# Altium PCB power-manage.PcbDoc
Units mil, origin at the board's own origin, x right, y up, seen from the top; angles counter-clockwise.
Board outline 3395.41 x 2057.23 mil, 4 copper layers (Top Layer, POWER, GND, Bottom Layer), stack 22.4 mil thick; 64 components, 38 nets, 210 pads, 100 vias.
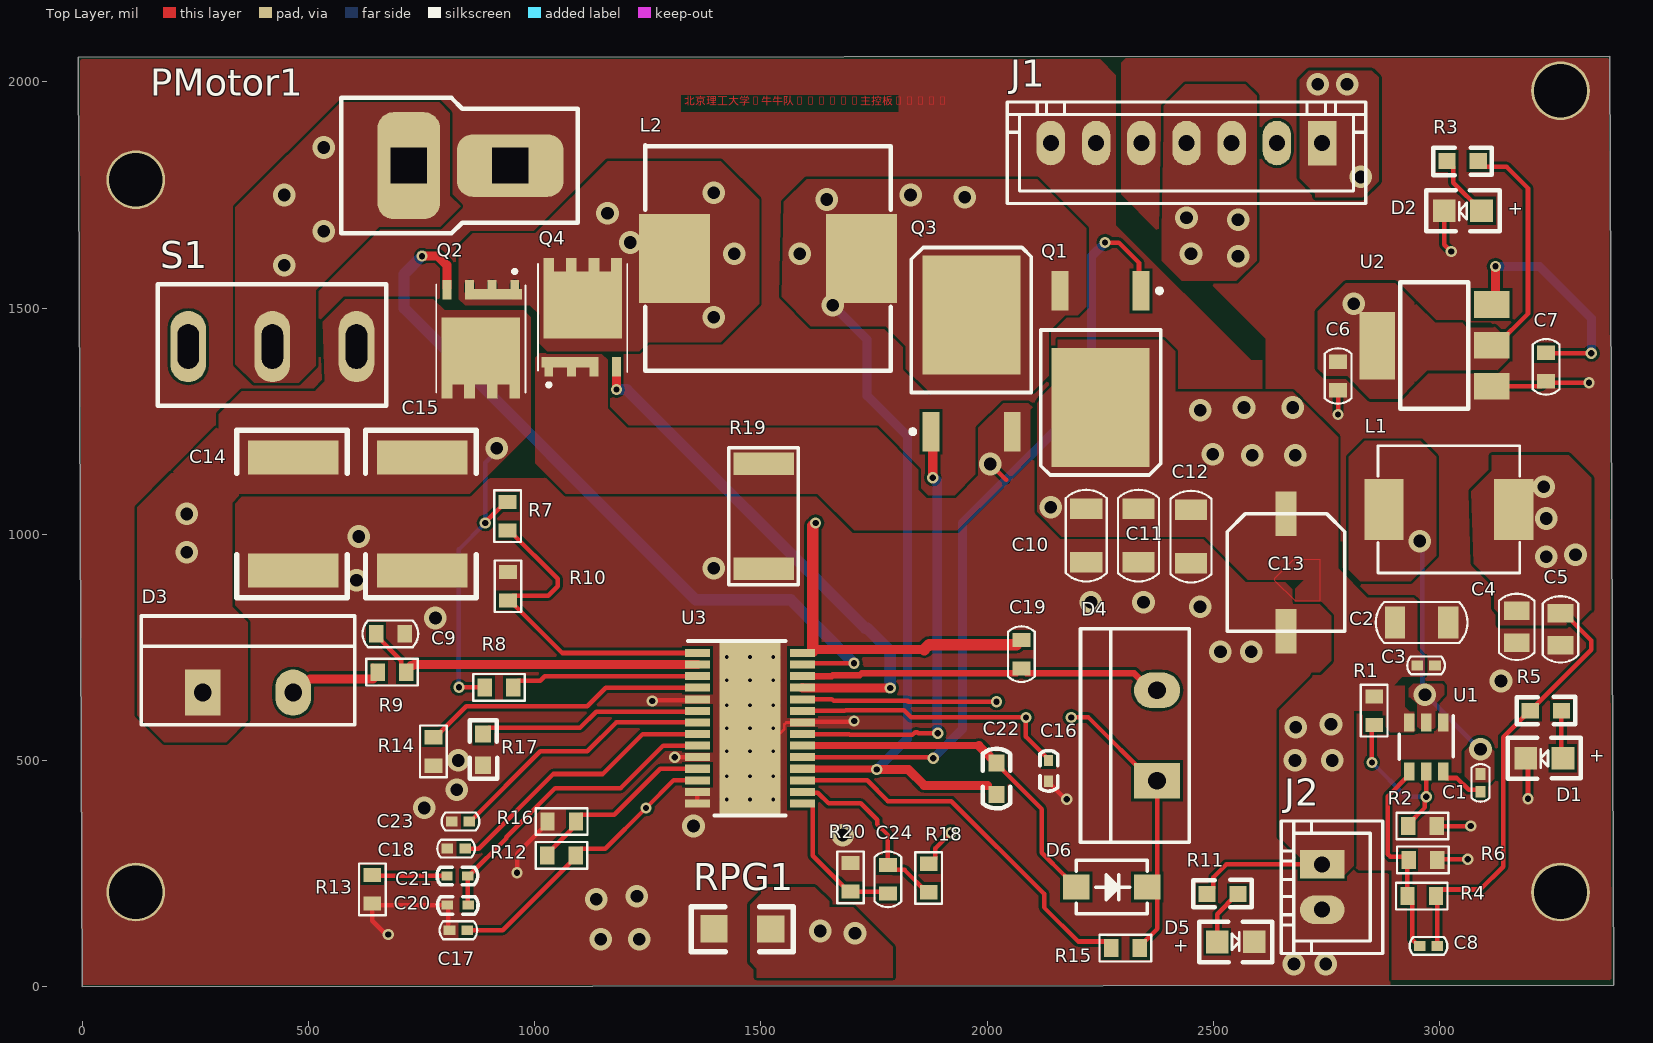
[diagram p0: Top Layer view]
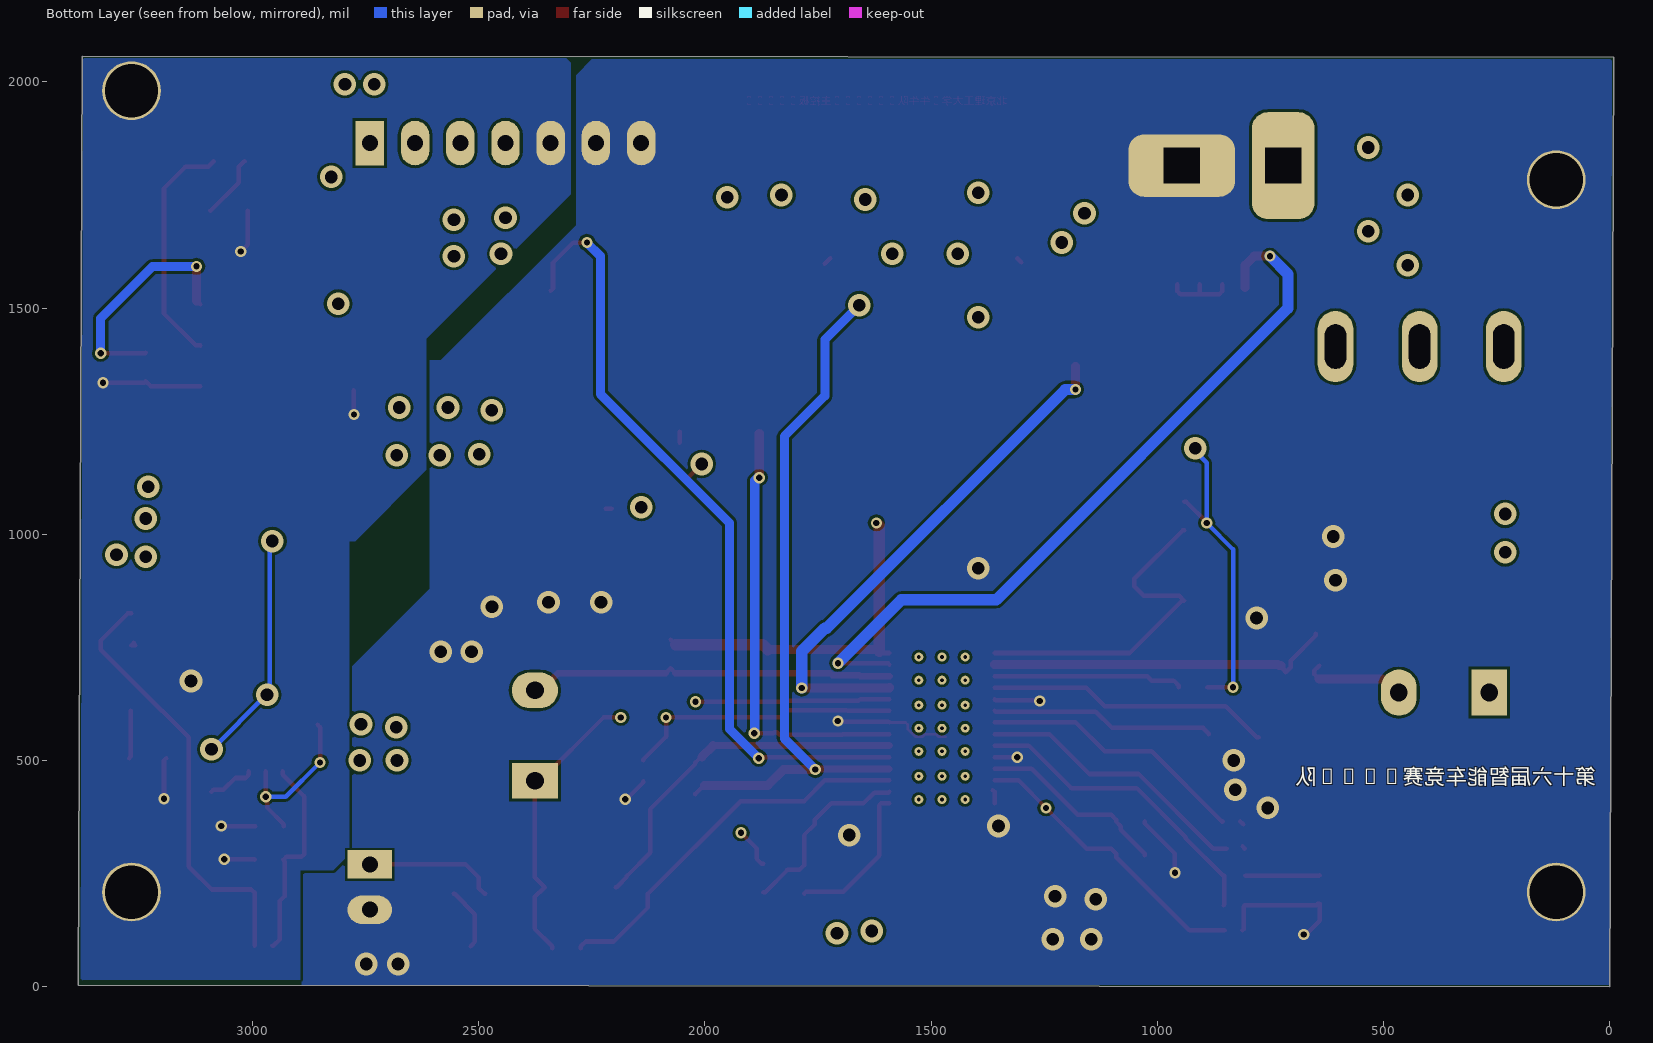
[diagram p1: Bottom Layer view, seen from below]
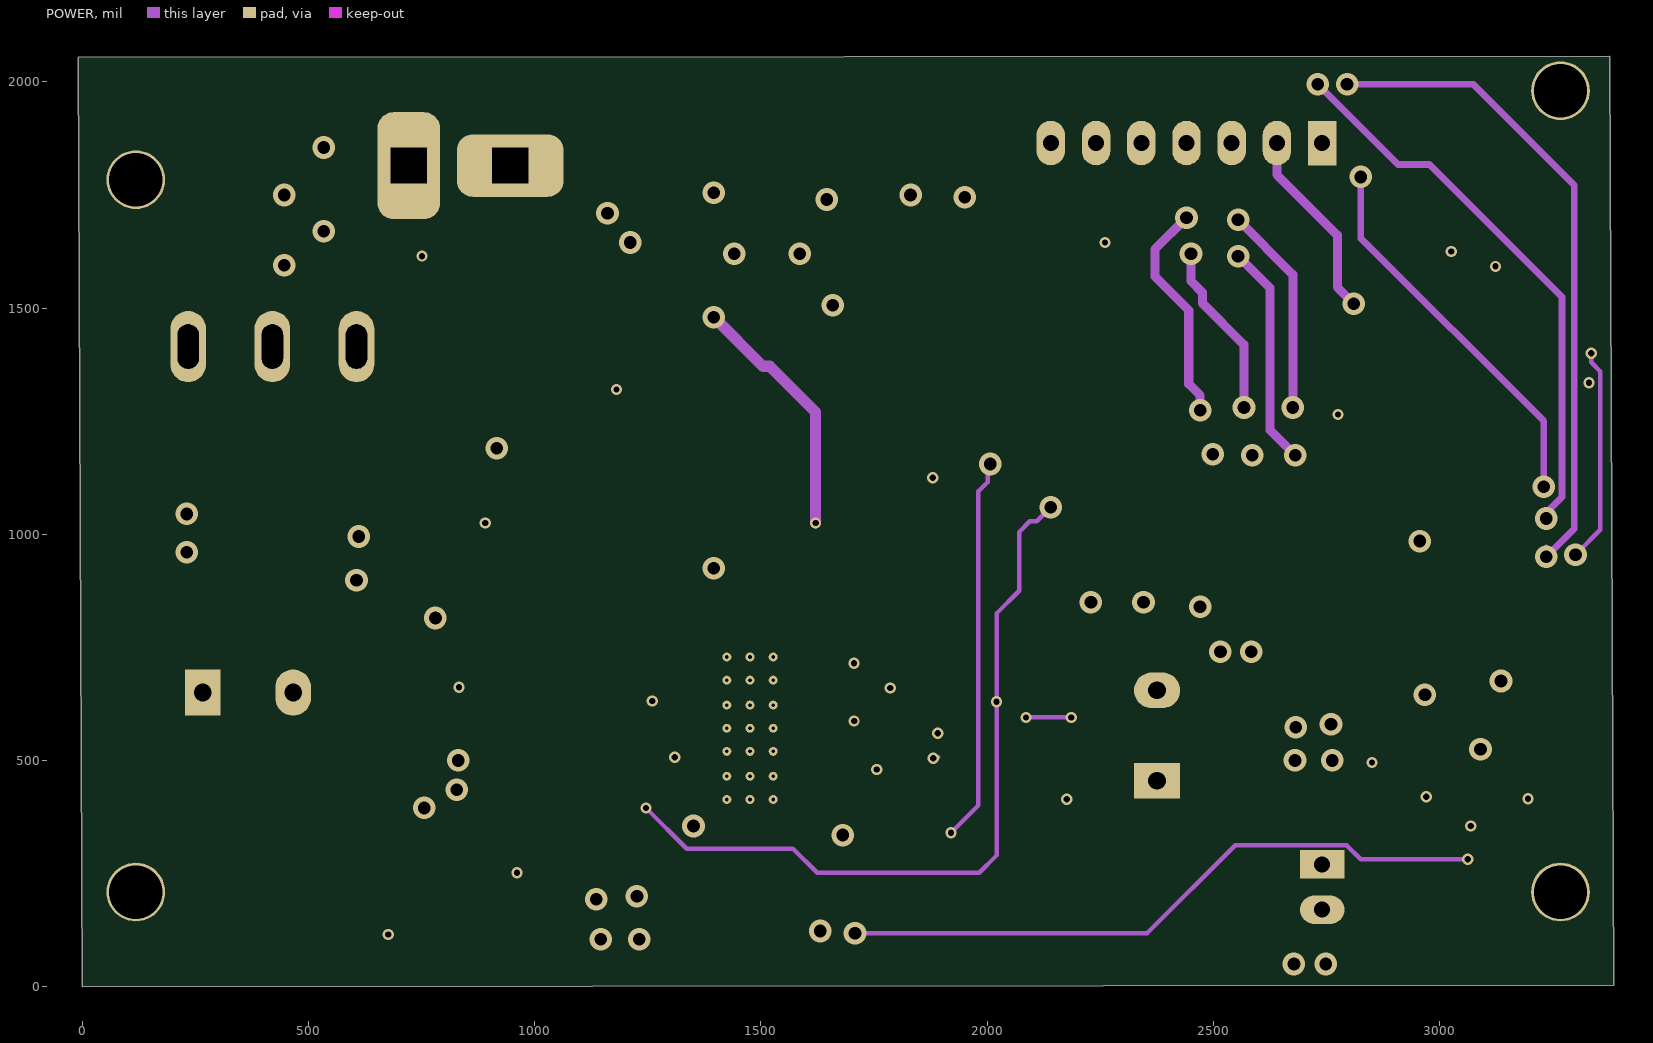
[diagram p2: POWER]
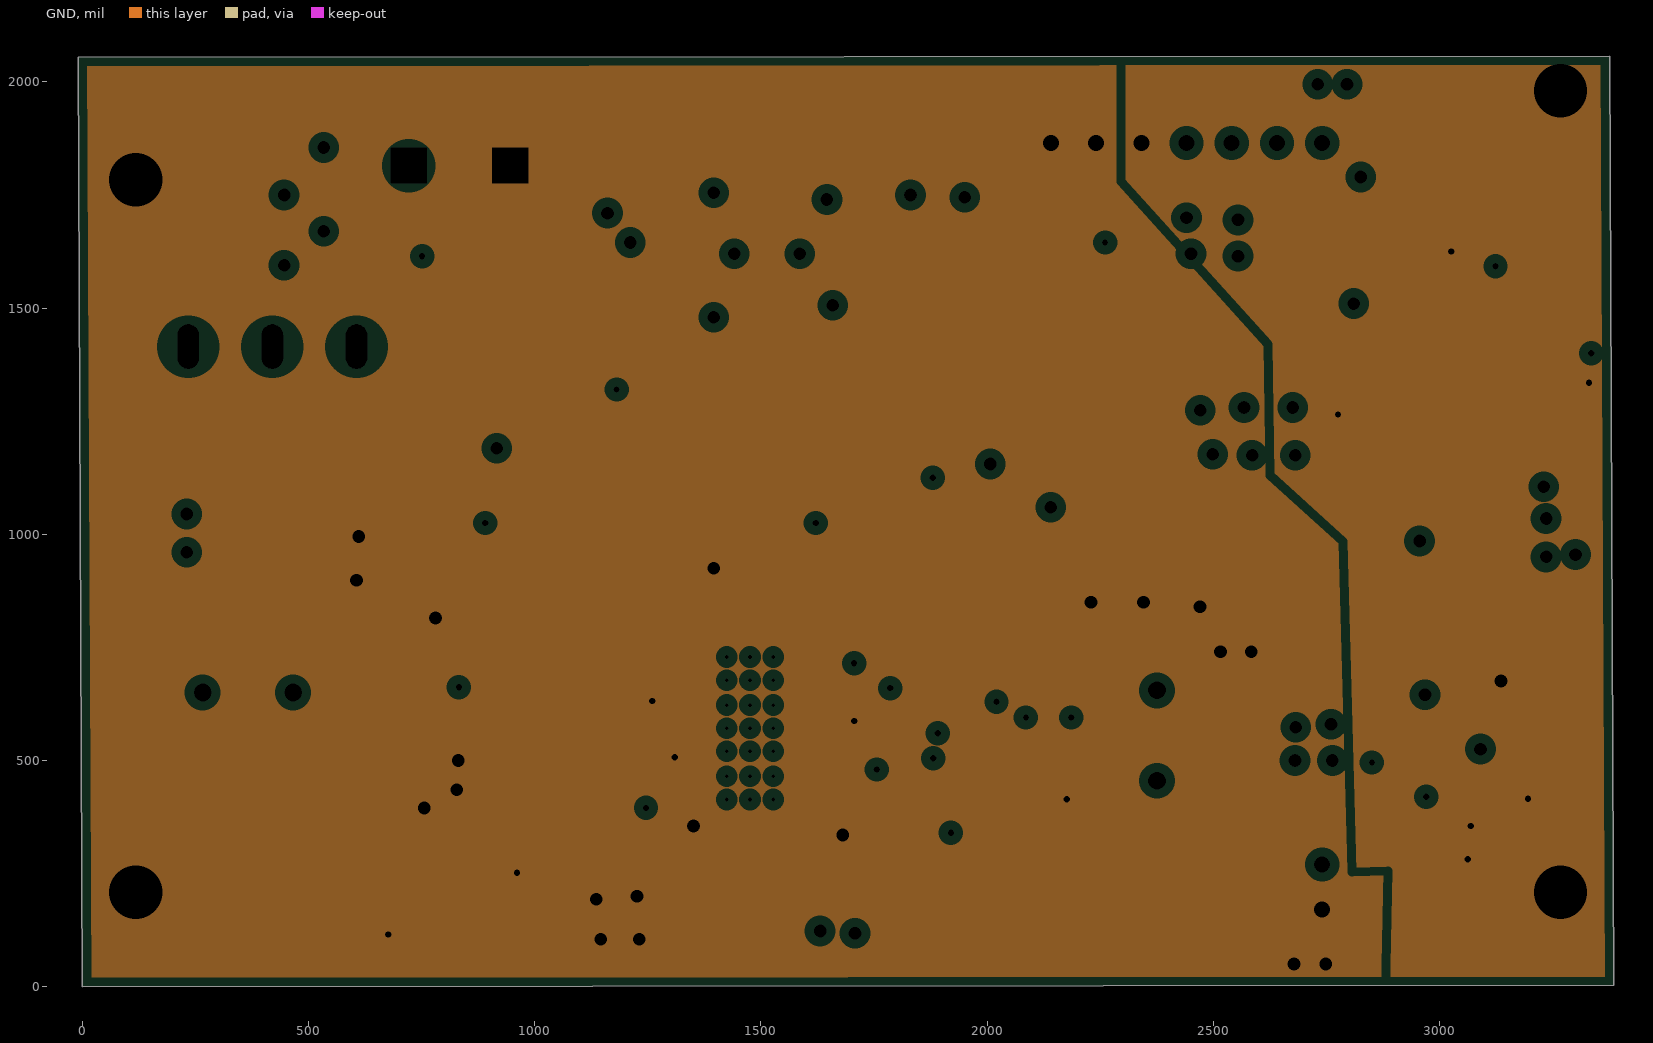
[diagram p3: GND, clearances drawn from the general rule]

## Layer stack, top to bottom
Top Solder: solder mask 0.4, Solder Resist, Dk 3.5
Top Layer: signal copper 1.4
Dielectric 2: prepreg 2.8, PP-006, Dk 4.1
POWER: signal copper 0.7
Dielectric 3: prepreg 2.8, PP-006, Dk 4.1
GND: plane copper 0.7, net AGND
Dielectric 1: dielectric 12.6, FR-4, Dk 4.8
Bottom Layer: signal copper 1.4
Bottom Solder: solder mask 0.4, Solder Resist, Dk 3.5

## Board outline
0,0 -9.59,2054.52 3376.24,2057.23 3385.83,2.71

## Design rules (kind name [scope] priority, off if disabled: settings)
Clearance [All] p1: gap=6 ignorepadtopadclearanceinfootprint=TRUE
HoleSize [All] p1: absolutevalues=TRUE maxlimit=400 minlimit=1 maxpercent=80.000 minpercent=20.000
MinimumSolderMaskSliver [All] p1: minsoldermaskwidth=2
PlaneClearance [All] p1: clearance=20
PlaneConnect [All] p1: planeconnectstyle=Direct reliefexpansion=20 reliefentries=4 reliefconductorwidth=10 reliefairgap=10
PolygonConnect [All] p1: connectstyle=Direct reliefconductorwidth=10 reliefentries=4 polygonreliefangle="90 Angle" airgapwidth=10
RoutingVias [All] p1: holewidth=14 width=25 viastyle="Through Hole" minholewidth=3 minwidth=3 maxholewidth=118.11 maxwidth=200
SilkToSilkClearance [All] p1: silktosilkclearance=2
SilkToSolderMaskClearance [IsPad] p1: minsilkscreentomaskgap=2 clearancetoexposedcopper=TRUE
SolderMaskExpansion [All] p1: expansion=4
Width [All] p1: maxlimit=100 minlimit=6 preferedwidth=10 toplayer_maxwidth=50 bottomlayer_maxwidth=50 minimp=50.000000 maximp=50.000000 favimp=50.000000
24 further rules are at their usual default settings.

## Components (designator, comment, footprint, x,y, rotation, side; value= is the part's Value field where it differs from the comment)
C1 "Cap" 0402-C 3090.89,450.36 r270 top value=0.1uF
C2 "Cap" 1206-C 2960.89,805.05 r180 top value=10uF
C3 "Cap" 0402-C 2970.58,710.05 r180 top value=0.1uF
C4 "Cap" 0805-C 3170.89,795.48 r270 top value=22uF
C5 "Cap" 0805-C 3267.76,790.05 r270 top value=22uF
C6 "Cap" 0603-C 2775.89,1350.05 r90 top value=10uF
C7 "Cap" 0603-C 3235.89,1370.05 r90 top value=10uF
C8 "Cap" 0402-C 2975.89,90.05 r180 top value=100pF
C9 "Cap" 0603-C 680.89,780.05 r180 top value=0.1uF
C10 "Cap" 1206-C 2219.24,997.01 r270 top value=22uF
C11 "Cap" 1206-C 2334.79,997.01 r270 top value=22uF
C12 "Cap" 1206-C 2450.89,995.05 r270 top value=22uF
C13 "Cap" "CAP-E SMD 6.6X6.6" 2660.89,785.21 r180 top value=270uF
C14 "C" C2220 465.89,1170.05 r270 top value=15uF
C15 "C" C2220 750.89,1170.05 r270 top value=15uF
C16 "Cap" C0402 2135.89,499.05 r270 top value="1uF 1mO"
C17 "Cap" 0402-C 831.21,124.57 r180 top value=0.1uF
C18 "Cap" 0402-C 826.21,305.05 r180 top value=15nF
C19 "Cap" 0603-C 2075.89,735.05 r270 top value=0.1uF
C20 "Cap" C0402 851.89,180.05 r180 top value=330pF
C21 "Cap" C0402 850.89,245.05 r180 top value=33nF
C22 "Cap" C0603 2020.89,425.05 r90 top value=100nF
C23 "Cap" 0402-C 835.89,365.05 r0 top value=470pF
C24 "Cap" 0603-C 1780.89,237.19 r270 top value=47pF
D1 "LED0" LED0805 3273.19,505.25 r180 top
D2 "LED0" LED0805 3093.19,1715.25 r180 top
D3 "SDURF" TO-220-AS 365.89,650.05 r0 top
D4 "STTH" TO-220-AS 2375.89,555.05 r90 top
D5 "LED0" LED0805 2508.59,98.73 r0 top
D6 "MBR0520" SOD-123 2275.66,220.05 r0 top
J1 "PIN7" XH7-2.54 2440.89,1865.05 r180 top
J2 "PIN2" XH2-2.54 2740.89,220.05 r270 top
L1 "Inductor Iron" IND-SMD_L7.8-W7.0_MAPM0630F 3020.89,1055.05 r180 top value=15uH
L2 "Inductor" IND-SMD_L13.8-W12.6_MHCC12050 1515.89,1610.05 r0 top value=4.7uH
PMotor1 "Header 2" PCBComponent_1 571.88,1964.66 r270 top
Q1 "BSC034N10LS5" TO252 2250.89,1365.05 r270 top
Q2 "BSC034N10LS5" BSC010N04LS6ATMA1 880.89,1431.62 r180 top
Q3 "BSC034N10LS5" TO252 1965.89,1400.05 r90 top
Q4 "BSC034N10LS5" BSC010N04LS6ATMA1 1105.89,1480.05 r0 top
R1 "Res1" 0603-R 2855.89,610.05 r90 top value=510K
R2 "Res1" 0603-R 2962.39,355.05 r180 top value=100K
R3 "Res2" R0603 3016.89,1825.05 r0 top value=40
R4 "Res1" 0603-R 2960.89,200.05 r0 top value=100K
R5 "Res2" R0603 3269.89,610.05 r180 top value=400
R6 "Res1" 0603-R 2963.49,280.05 r180 top value=13K
R7 "Res1" 0603-R 939.83,1040.05 r90 top value=270K
R8 "Res1" 0603-R 920.89,661.55 r180 top value=2K
R9 "10R" 0603-R 684.4,695.05 r180 top
R10 "Res1" 0603-R 940.89,885.05 r270 top value=180K
R11 "Res2" R0603 2554.89,205.05 r180 top value=1.6K
R12 "Res1" 0603-R 1059.24,290.05 r0 top value=270K
R13 "Res1" 0603-R 640.89,215.05 r90 top value=10K
R14 "Res1" 0603-R 775.89,520.05 r90 top value=91K
R15 "Res1" 0603-R 2305.89,85.05 r0 top value=270K
R16 "Res1" 0603-R 1059.59,365.05 r180 top value=20K
R17 "Res1" R0603 885.89,489.44 r90 top value=27K
R18 "Res1" 0603-R 1870.89,240.05 r270 top value=100R
R19 "Res1" 2512-R 1505.89,1040.05 r90 top value=3.44mR
R20 "Res1" 0603-R 1698.1,241.55 r270 top value=100R
RPG1 "Res2" R1206 1450.89,130.05 r180 top value=0Ω
S1 "SW-SPDT" SW-TO3 419.89,1415.05 r270 top
U1 "TPS54202DDCR" DDC0006A_N 2970.89,530.05 r270 top value=Value
U2 "AMS1117-3.3V" SOT223 2985.89,1415.05 r90 top
U3 "LM5176PWPR" PWP0028C_N 1475.89,571.23 r0 top value=Value

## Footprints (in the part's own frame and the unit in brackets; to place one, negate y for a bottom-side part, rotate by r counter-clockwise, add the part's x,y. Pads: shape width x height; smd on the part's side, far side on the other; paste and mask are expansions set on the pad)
0402-C [mm]
  rect 0.65x0.55 smd: 1(-0.5,0) 2(0.5,0)
  silkscreen extent -1.06,-0.5 1.06,0.5
0603-C [mm]
  rect 0.8x1 smd: 1(-0.8,0) 2(0.8,0)
  silkscreen extent -1.56,-0.75 1.56,0.75
0603-R [mm]
  rect 0.8x1 smd: 1(-0.8,0) 2(0.8,0)
  silkscreen extent -1.45,-0.75 1.45,0.75
0805-C [mm]
  rect 1.05x1.45 smd: 1(-0.9,0) 2(0.9,0)
  silkscreen extent -1.86,-1 1.86,1
1206-C [mm]
  rect 1.15x1.8 smd: 1(-1.5,0) 2(1.5,0)
  silkscreen extent -2.58,-1.15 2.58,1.15
2512-R [mm]
  rect 1.25x3.4 smd: 1(-2.95,0) 2(2.95,0)
  silkscreen extent -3.85,-1.95 3.85,1.95
BSC010N04LS6ATMA1 [mm]
  rect 0.5x1.1 smd: 1(1.905,-2.775)
  rect 0.6x0.8 smd: 2(-1.905,2.925) 2(-0.635,2.925) 2(0.635,2.925) 2(1.905,2.925)
  rect 4.41x3.75 smd: 2(0,0.675)
  rect 0.5x0.5 smd: 3(-1.905,-3.075) 3(-0.635,-3.075) 3(0.635,-3.075)
  rect 3.2x0.6 smd: 3(-0.715,-2.525)
  silkscreen extent -2.5,-3.9 2.5,3, body extent -2.5,-3.27 2.5,3.26, height 1.2
C0402 [mil]
  rect 25x20 smd: 1(-1,0) 2(45,0)
  silkscreen extent -23,-19 67,20, body extent 2,-10 42,10, height 20
C0603 [mil]
  rect 38x35 smd: 1(0,0) 2(69,0)
  silkscreen extent -31,-30 101,30, body extent 4,-16 67,16, height 12
C2220 [mil]
  rect 75x200 smd: 1(0,0) 2(250,0)
  silkscreen extent -60,-125 310,120, body extent 11,-98 235,98, height 91
"CAP-E SMD 6.6X6.6" [mm] "SMDC"
  rect 1.2x2.5 smd: 1(0,0) 2(0,-6.6)
  silkscreen extent -3.3,-6.6 3.3,0, body extent -3.27,-6.8 3.33,0.2, height 5.2
DDC0006A_N [mm]
  rect 1x0.6 smd paste+0 mask+0: 1(-1.375,0.95) 2(-1.375,0) 3(-1.375,-0.95) 4(1.375,-0.95) 5(1.375,0) 6(1.375,0.95)
  silkscreen extent -1.75,-1.52 0.7,1.53, body extent 0,0 0.25,0.25, height 0.25
IND-SMD_L7.8-W7.0_MAPM0630F [mm]
  rect 2.194x3.42 smd: 1(3.643,0) 2(-3.643,0)
  silkscreen extent -3.98,-3.58 3.98,3.58
IND-SMD_L13.8-W12.6_MHCC12050 [mm]
  rect 4x5 smd: 1(-5.25,0) 2(5.25,0)
  silkscreen extent -6.9,-6.3 6.9,6.35
LED0805 [mil] "1/8W"
  rect 50x50 smd: 1(0,0) 2(82.3,0.2)
  silkscreen extent -40,-45 122,45, body extent 2,-25 80,25, height 20
PCBComponent_1 [mm]
  rrect50% 6x3.5 hole 2 square: 1(3.8,3.8)
  rrect50% 3.5x6 hole 2 square: 2(3.8,9.5)
  silkscreen extent 0,0 7.6,13.3
PWP0028C_N [mm]
  rect 1.4x0.45 smd paste+0 mask+0: 1(-2.95,4.225) 2(-2.95,3.575) 3(-2.95,2.925) 4(-2.95,2.275) 5(-2.95,1.625) 6(-2.95,0.975) 7(-2.95,0.325) 8(-2.95,-0.325) 9(-2.95,-0.975) 10(-2.95,-1.625) 11(-2.95,-2.275) 12(-2.95,-2.925) 13(-2.95,-3.575) 14(-2.95,-4.225) 15(2.95,-4.225) 16(2.95,-3.575) 17(2.95,-2.925) 18(2.95,-2.275) 19(2.95,-1.625) 20(2.95,-0.975) 21(2.95,-0.325) 22(2.95,0.325) 23(2.95,0.975) 24(2.95,1.625) 25(2.95,2.275) 26(2.95,2.925) 27(2.95,3.575) 28(2.95,4.225)
  rect 3.4x9.7 smd paste-1.7 mask-1.702: 29(0,0)
  round 0.5 hole 0.203 mask-0.152: V(-1.3,-1.3) V(-1.3,0) V(-1.3,1.3) V(0,-1.3) V(0,0) V(0,1.3) V(1.3,-1.3) V(1.3,0) V(1.3,1.3)
  round 0.5 hole 0.203 mask-0.241: V(-1.3,2.7) V(-1.3,4) V(-1.3,-4) V(-1.3,-2.7) V(0,2.7) V(0,-2.7) V(0,4) V(0,-4) V(1.3,2.7) V(1.3,4) V(1.3,-4) V(1.3,-2.7)
  silkscreen extent -3.5,-4.9 2,4.9, body extent 0,0 0.25,0.25, height 0.25
R0603 [mil] "1/10W"
  rect 38x35 smd: 1(0,0) 2(69,0)
  silkscreen extent -30,-31 99,30, body extent 4,-16 66,16, height 18
R1206 [mil] "1/4W"
  rect 60x60 smd: 1(-71,3) 2(55,2)
  silkscreen extent -121,-47 105,53, body extent -71,-29 55,33, height 24
SOD-123 [mm]
  rect 1.5x1.4 smd: 1(2,0) 2(-2,0)
  silkscreen extent -2,-1.5 2,1.5
SOT223 [mil]
  rect 59x79 smd: 1(-88,-130) 2(2.55,-130) 3(93.1,-130)
  rect 150x79 smd: 2(1.88,123.54)
  silkscreen extent -137,-78 143,72, body extent -126,-139 130,135, height 67
SW-TO3 [mm]
  oval 4x2 hole 1.2 slot 2.5 at 0 deg: 1(0,-4.724) 2(0,0) 3(0,4.724)
  silkscreen extent -3.5,-6.43 3.33,6.39, body extent -3.43,-6.36 3.43,6.35, height 28.55
TO252 [mm] "D-PAK  / SOT-428"
  rect 2.2x0.95 smd: 1(-4.4,2.28) 3(-4.4,-2.28)
  rect 6.7x5.5 smd: 2(2.15,0)
  silkscreen extent -4.52,-3.35 5.94,3.43, body extent -4.47,-3.3 4.78,3.3, height 2.31
TO-220-AS [mm]
  rect 2x2.6 hole 1: 1(-2.54,0)
  oval 2x2.6 hole 1: 2(2.54,0)
  silkscreen extent -6,-1.8 6,4.3
XH2-2.54 [mm]
  rect 1.6x2.5 hole 0.9: 1(-1.27,0)
  oval 1.6x2.5 hole 0.9: 2(1.27,0)
  silkscreen extent -3.72,-2.3 3.72,3.4
XH7-2.54 [mm]
  rect 1.6x2.5 hole 0.9: 1(-7.62,0)
  oval 1.6x2.5 hole 0.9: 2(-5.08,0) 3(-2.54,0) 4(0,0) 5(2.54,0) 6(5.08,0) 7(7.62,0)
  silkscreen extent -10.07,-2.3 10.07,3.4

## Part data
C1 C2 C3 C4 C5 C6 C7 C8 C9 C10 C11 C12 C13 C16 C17 C18 C19 C20 C21 C22 C23 C24: "Capacitor"
C14 C15: library part "Cap Pol1", "Polarized Capacitor (Radial)"
D1 D2 D5: "Typical INFRARED GaAs LED"
D3 D4 D6: library part "Diode 1N4003", "1 Amp General Purpose Rectifier"
L1: "Magnetic-Core Inductor"
PMotor1: "Header, 2-Pin"
Q1 Q2 Q3 Q4: library part NMOS-2, "N-Channel Power MOSFET"
R1 R2 R3 R4 R5 R6 R7 R8 R10 R11 R12 R13 R14 R15 R16 R17 R18 R19 R20 RPG1: "Resistor"
R9: library part Res1, "Resistor"
S1: "SPDT Subminiature Toggle Switch, Right Angle Mounting, Vertical Actuation"
U1 U3: "No Description Available", Manufacturer="Texas Instruments"
U2: library part AMS1117

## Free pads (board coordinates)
  round 129.92 hole 118.11: 4(118.13,209.08) 4(118.13,1783.88) 4(3267.74,209.08) 4(3267.74,1980.73)

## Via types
v1: diameter 50, hole 28, Top Layer to Bottom Layer, 67 vias
v2: diameter 25, hole 14, Top Layer to Bottom Layer, 33 vias

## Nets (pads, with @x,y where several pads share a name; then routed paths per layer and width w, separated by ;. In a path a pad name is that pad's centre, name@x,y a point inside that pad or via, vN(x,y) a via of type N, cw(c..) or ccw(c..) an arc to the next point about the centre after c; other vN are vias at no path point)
AGND: C9.1 C10.2 C11.2 C12.2 C13.1 C14.2 C15.2 C16.2 C17.2 C18.2 C20.2 C23.1 D5.2 J1.6 J1.7 J2.2 pad.4@118.13,209.08 pad.4@118.13,1783.88 PMotor1.2 R10.1 R13.1 R14.1 R16.2 R17.1 R19.1 R20.1 RPG1.2 U3.5 U3.10 U3.13 U3.14 U3.22 U3.29 | length 970.5
  Top Layer w6: U3.29@1468.09,552.39 1483.7,552.39 1489.22,557.91 1513.75,557.91 1519.27,552.39 1534.88,552.39 1551.82,569.33 1551.82,579.61 1556.24,584.03 U3.22
  Top Layer w10: v2(675.89,115.05) 671.83,115.05 640.89,145.99 R13.1 644.83,183.55 648.33,180.05 C20.2 809.21,177.73 809.21,126.89 C17.2 ; C18.2 C18.2@811.37,309.89 ; C23.1@810.38,359.22 811.37,360.21 C23.1 ; v2(960.89,251.55) 960.89,293.91 1028.1,361.11 R16.2 ; v2(1259.57,631.53) 1261.41,633.37 1357.91,633.37 U3.5 ; v2(1309.62,507.25) U3.10 ; U3.14 U3.13 U3.13@1363.61,434.34 ; U3.22 1593.64,585.63 1704.4,585.63 v2(1706,587.23) ; C16.2 2135.89,451.55 2173.39,414.05 v2(2175.89,414.05)
  other v1: 2678.39,50.05 2748.39,50.05 1145.89,105.05 1230.89,105.05 1135.89,193.05 1225.89,200.05 1681.24,335.05 1350.89,355.05 755.89,395.05 827.37,435.36 830.89,500.05 2515.89,740.05 2583.74,740 780.46,815.05 2470.89,840.05 2229.61,850.05 2345.89,850.05 605.89,898.47 1395.89,925.05 610.89,995.05
NetC1_1: C1.1 L1.1 U1.2 | length 532.1
  Bottom Layer w10: v1(2956.21,985.05) 2962.12,979.14 2962.12,650.96 v1(2968.02,645.05) ; v1@2968.02,659.66 v1(2968.02,645.05) ; v1(3090.89,525.05) 3089.46,525.05 2969.46,645.05 v1(2968.02,645.05)
NetC1_2: C1.2 U1.6 | length 105.9
  Top Layer w10: U1.6 3008.29,468.04 3015.11,461.23 3038.71,461.23 3065.07,434.87 3086.7,434.87 C1.2
NetC8_2: C8.2 R4.1 R6.2 U1.4 | length 457.6
  Top Layer w10: U1.4 2933.49,468.04 2885.89,420.44 2885.89,292.77 2891.75,286.91 2925.14,286.91 R6.2 2929.4,277.45 R4.1 2940.14,189.3 2940.14,104.14 2954.24,90.05 C8.2
NetC9_2: C9.2 R9.1 U3.2 | length 765.7
  Top Layer w10: C9.2 649.4,776.11 705.14,720.36 705.14,705.8 R9.1 720.89,700.05 720.89,703.99 R9.1@726.64,709.73 ; R9.1@730.58,709.73 732.82,711.98
  Top Layer w20: R9.1@726.64,709.73 R9.1@730.58,709.73 ; 732.82,711.98 U3.2
NetC18_1: C18.1 U3.8 | length 618.8
  Top Layer w10: C18.1 875.89,305.05 1040.89,470.05 1150.09,470.05 1238.47,558.44 U3.8
NetC19_1: C19.1 L2.1 Q2.3 Q4.2 U3.28 | length 1503.7
  Top Layer w10: Q2.3@855.89,1552.69 855.89,1537.84 862.7,1531.03 Q2.3@909.04,1531.03 ; Q2.3@905.89,1552.69 905.89,1534.18 Q2.3@909.04,1531.03 ; Q2.3@955.89,1552.69 955.89,1537.84 949.08,1531.03 Q2.3@909.04,1531.03 ; L2.1@1300.89,1601.74 L2.1 ; U3.28 U3.28@1610.74,737.57 ; U3.28@1614.59,741.43 U3.28@1618.22,745.05 ; v2@1614.59,1018.75 v2(1620.89,1025.05) ; C19.1@2065.14,755.8 C19.1
  Top Layer w20: U3.28@1618.22,745.05 1860.89,745.05
  Top Layer w25: U3.28@1614.59,741.43 v2@1614.59,1018.75 ; 1860.89,745.05 1871.64,755.8 C19.1@2065.14,755.8
  POWER w25: v1(1395.89,1480.05) 1504.72,1371.22 1519.72,1371.22 1620.89,1270.05 v2(1620.89,1025.05)
  other v1: 1440.89,1620.05 1210.89,1645.05 1160.89,1710.05 1395.89,1755.05
NetC19_2: C19.2 D4.2 U3.26 | length 811.1
  Top Layer w10: 1656.84,686.39 1658.75,688.3 ; 1718.75,688.3 1723.26,692.81 ; C19.2@2065.14,692.81 C19.2 C19.2@2086.64,692.81 ; D4.2@2362.7,655.05 D4.2
  Top Layer w15: U3.26 1656.84,686.39 ; 1658.75,688.3 1718.75,688.3 ; 1723.26,692.81 C19.2@2065.14,692.81 ; C19.2@2086.64,692.81 2324.95,692.81 D4.2@2362.7,655.05
NetC20_1: C20.1 C21.1 U3.9 | length 694.2
  Top Layer w10: C20.1 852.39,180.55 852.39,244.55 C21.1 854.39,245.05 936.81,327.47 936.81,330.41 1045.45,439.05 1189.89,439.05 1283.69,532.84 U3.9
NetC21_2: C21.2 R13.2 | length 165.6
  Top Layer w10: R13.2 642.39,245.05 C21.2
NetC22_1: C22.1 L2.2 Q1.3 Q3.2 U3.18 | length 1594.1
  Top Layer w10: U3.18 U3.18@1592.84,480.86 ; L2.2 L2.2@1734.87,1597.76 ; v2@1755.09,480.86 v2(1755.89,480.05) ; 2000.89,445.05 2006.89,439.05 2008.39,439.05 2020.89,426.55 C22.1
  Top Layer w15: U3.18@1592.84,480.86 v2@1755.09,480.86
  Top Layer w20: v2(1755.89,480.05) 1825.89,480.05 1860.89,445.05 2000.89,445.05
  Bottom Layer w20: v1(1658.75,1506.62) 1734.87,1430.51 1734.87,1306.07 1824.42,1216.53 1824.42,548.57 v2(1755.89,480.05)
  other v1: 1585.89,1620.05 1645.89,1740.05 1950.89,1745.05 1830.89,1750.05
NetC22_2: C22.2 D6.2 U3.20 | length 793.9
  Top Layer w10: C22.2@2006.89,508.05 2008.39,508.05 2020.89,495.55 C22.2 2020.89,492.55 2120.89,392.55 2120.89,296.07 2172.39,244.58 2172.39,242.61 2194.95,220.05 D6.2
  Top Layer w15: U3.20 1982.1,532.84
  Top Layer w20: 1982.1,532.84 C22.2@2006.89,508.05
NetC23_2: C23.2 U3.7 | length 594.9
  Top Layer w10: C23.2 857.55,365.05 1012.55,520.05 1115.89,520.05 1179.87,584.03 U3.7
NetC24_1: C24.1 R18.2 U3.16 | length 415.5
  Top Layer w10: U3.16 1593.77,428.75 1625.81,428.75 1649.51,405.05 1720.89,405.05 1757.39,368.55 1757.39,358.55 1780.89,335.05 C24.1 1791.64,257.94 1817.57,257.94 1866.96,208.55 R18.2
NetC24_2: C24.2 R20.2 U3.15 | length 336.6
  Top Layer w10: U3.15 1610.74,404.89 1614.59,401.03 1614.59,289.62 1694.16,210.05 R20.2 1776.54,210.05 C24.2
NetD1_1: D1.1 R5.1 | length 106.2
  Top Layer w10: R5.1 3269.89,508.55 D1.1
NetD2_1: D2.1 R3.1 | length 142.3
  Top Layer w10: R3.1 3018.39,1825.05 3030.89,1812.55 3030.89,1777.55 D2.1
NetD3_2: D3.2 R9.2 | length 227.1
  Top Layer w10: D3.2 472.68,650.05 503,680.36 ; R9.2@642.15,680.36 652.9,691.11 R9.2 652.9,698.99 R9.2@642.15,709.73
  Top Layer w20: 503,680.36 R9.2@642.15,680.36
NetD5_1: D5.1 R11.1 | length 139.8
  Top Layer w10: D5.1@2518.07,89.25 D5.1 2508.59,160.25 2553.39,205.05 R11.1
NetQ1_1: Q1.1 U3.19 | length 1761.2
  Top Layer w10: U3.19 1592.33,507.55 1878.39,507.55 v2(1880.89,505.05) ; v2(2260.89,1645.05) 2290.89,1645.05 2335.89,1600.05 2335.89,1543.04 Q1.1
  POWER w10: v2(1880.89,505.05) 1883.1,507.25 v2@1892.35,507.25
  Bottom Layer w10: v2(2260.89,1645.05) v2@2263.76,1647.92
  Bottom Layer w20: v2(1880.89,505.05) 1945.89,570.05 1945.89,1025.05 2230.89,1310.05 2230.89,1614.95 2260.89,1644.95 v2(2260.89,1645.05)
NetQ2_1: Q2.1 U3.27 | length 1686.4
  Top Layer w10: Q2.1 808.37,1543.36 Q2.1@805.89,1545.84 ; U3.27 1595.11,715.05 v2(1705.89,715.05)
  Top Layer w20: v2(750.89,1615.05) 785.89,1615.05 805.89,1595.05 Q2.1@805.89,1545.84
  Bottom Layer w25: v2(750.89,1615.05) 710.89,1575.05 710.89,1500.05 1355.89,855.05 1565.89,855.05 v2(1705.89,715.05)
NetQ3_1: Q3.1 U3.21 | length 978.3
  Top Layer w10: U3.21 1694.8,558.44 1696.71,556.53 1835.04,556.53 1840.89,562.38 1845.89,562.38 1848.23,560.05 v2(1890.89,560.05) ; Q3.1 Q3.1@1879.95,1223
  Top Layer w20: v2(1879.95,1125.05) Q3.1@1879.95,1223
  Bottom Layer w10: v2(1879.95,1125.05) v2@1884.01,1125.05 ; v2@1889.87,561.07 v2(1890.89,560.05)
  Bottom Layer w20: v2@1884.01,1125.05 1889.87,1119.19 v2@1889.87,561.07
NetQ3_3: Q3.3 Q4.3 R18.1 R19.2 | length 1016.8
  Top Layer w10: R18.1 1874.83,271.55 1885.58,282.29 1885.58,305.48 v2(1920.14,340.05) ; v1(2006.89,1155.54) 2041.96,1120.47 ; Q3.3@2055.66,1202.21 Q3.3
  POWER w10: v2(1920.14,340.05) 1980.89,400.8 1980.89,1095.05 2001.38,1115.54 2001.38,1150.03 v1(2006.89,1155.54)
NetQ4_1: Q4.1 U3.25 | length 1171.1
  Top Layer w20: v2(1180.89,1320.05) Q4.1 ; U3.25 1592.41,660.42 1785.52,660.42 v2(1785.89,660.05)
  Bottom Layer w25: v2(1180.89,1320.05) 1203.1,1320.05 1730.89,792.25 1735.23,792.25 1785.89,741.59 v2(1785.89,660.05)
NetR1_1: R1.1 R2.2 U1.5 | length 373.8
  Top Layer w10: v2(2850.89,495.55) 2850.89,573.55 R1.1 ; R2.2 2930.89,358.99 2968.02,396.12 2968.02,417.18 v2(2970.89,420.05) U1.5
  Bottom Layer w10: v2(2850.89,495.55) 2926.39,420.05 v2(2970.89,420.05)
NetR7_1: R7.1 R10.2 U3.1 | length 761.8
  Top Layer w10: R7.1 943.77,1008.55 1050.89,901.43 1050.89,885.05 1030.14,864.3 951.64,864.3 R10.2 944.83,853.55 1060.81,737.57 U3.1
NetR8_1: R8.1 U3.3 | length 420
  Top Layer w10: R8.1 952.39,665.48 963.14,676.23 1012.07,676.23 1022.23,686.39 U3.3
NetR12_1: R12.1 R16.1 U3.11 | length 420.5
  Top Layer w10: R12.1 1027.74,293.99 1080.34,346.58 1080.34,354.3 R16.1 1091.09,368.99 1101.84,379.73 1175.58,379.73 1277.51,481.66 U3.11
NetR14_2: R14.2 U3.4 | length 629.1
  Top Layer w10: R14.2 779.83,551.55 848.33,620.05 1115.89,620.05 1156.64,660.8 U3.4
NetR15_1: R15.1 U3.17 | length 855.9
  Top Layer w10: U3.17 1734.87,456.07 1780.89,410.05 1920.89,410.05 2125.89,205.05 2125.89,175.05 2201.21,99.73 2263.65,99.73 2274.4,88.99 R15.1
NetR17_2: R17.2 U3.6 | length 495.9
  Top Layer w10: R17.2 885.89,558.73 898.39,571.23 898.39,572.44 1100.07,572.44 1135.66,608.03 1358.16,608.03 U3.6
PIN: PMotor1.1 S1.2
  other v1: 445.89,1595.05 533.39,1670.05 445.89,1750.05 533.39,1855.05
Power-DRV: C14.1 C15.1 D3.1 Q2.2 R7.2 R8.2 S1.3 | length 689.2
  Top Layer w10: v2(832.39,661.55) R8.2 ; v2(890.89,1025.05) 890.89,1026.55 935.89,1071.55 R7.2
  Bottom Layer w10: v2(832.39,661.55) 832.39,966.55 v2(890.89,1025.05) 890.89,1158.48 915.89,1183.48 v1(915.89,1190.05)
  other v1: 230.89,960.05 230.89,1045.05
SGND: C2.1 C3.1 C4.2 C5.2 C6.1 C7.1 D1.2 D2.2 J1.5 pad.4@3267.74,209.08 pad.4@3267.74,1980.73 R2.1 R6.1 RPG1.1 U1.1 U2.1 | length 2070.2
  Top Layer w10: v2(2775.89,1264.97) C6.1 ; R2.1 v2(3069.27,355.05) ; R6.1 2996.2,281.27 v2(3062.58,281.27) ; D2.2 3010.89,1640.05 v2(3025.89,1625.05) ; U2.1 3116.65,1327.81 3225.14,1327.81 C7.1 3239.4,1335.05 v2(3330.89,1335.05) ; D1.2 3195.89,500.05 v2(3195.89,415.05) ; C5.2@3259.89,754.61 C5.2 C5.2@3262.33,760.05
  POWER w10: v1(1708.1,117.8) 2353.64,117.8 2548.39,312.55 2794.66,312.55 2825.94,281.27 v2(3062.58,281.27)
  other v1: 1630.89,123.05 3136.24,675.75
VCC: C16.1 D4.1 D6.1 R15.2 U3.23 | length 1368.9
  Top Layer w10: U3.23 1685.7,609.62 1687.61,611.53 1816.13,611.53 1832.61,595.05 v2(2085.89,595.05) 2085.89,552.55 2135.89,502.55 C16.1 ; v2(2185.89,595.05) 2224.08,595.05 2364.08,455.05 D4.1 2375.89,241.55 D6.1 2375.89,198.55 2375.89,127.49 2337.39,88.99 R15.2
  POWER w10: v2(2085.89,595.05) v2(2185.89,595.05)
VCC_3.3V: C6.2 J1.2 R3.2 U2.2 | length 947.7
  Top Layer w10: R3.2 3098.39,1812.55 3148.39,1812.55 3195.89,1765.05 3195.89,1487.6 3125.89,1417.6 3115.89,1417.6 U2.2@3115.22,1416.93
  POWER w20: J1.2 2640.89,1795.05 2774.57,1661.38 2774.57,1546.38 v1(2810.89,1510.05)
VCC_5V: C4.1 C5.1 C7.2 C8.1 J1.1 L1.2 R4.2 R5.2 U2.3 | length 5549.2
  Top Layer w10: C8.1 2995.58,207.18 3003.14,214.73 3090.58,214.73 3140.89,265.05 3140.89,551.55 3199.39,610.05 R5.2 3335.89,745.05 3335.89,765.22 3275.64,825.48 C5.1 ; U2.3 U2.3@3124.06,1516.32 ; C7.2 3237.39,1400.05 v2(3335.89,1400.05)
  Top Layer w20: U2.3@3124.06,1516.32 v2(3124.06,1592.23)
  POWER w10: J1.1 J1.1@2759.93,1846.02 ; v1(3235.89,950.05) v1@3235.89,972.63 ; v1(3235.89,1035.05) 3235.89,1052.23 v1@3241.24,1052.23 ; v1(3300.89,955.05) 3355.89,1010.05 3355.89,1360.05 3335.89,1380.05 v2(3335.89,1400.05)
  POWER w15: v1(2730.89,1995.05) 2908.39,1817.55 2978.39,1817.55 3271.24,1524.7 3271.24,1082.23 v1@3241.24,1052.23 ; v1(2795.89,1995.05) 3074.27,1995.05 3298.31,1771.01 3298.31,1012.47 v1(3235.89,950.05) ; v1(2825.89,1790.05) 2825.89,1655.05 3230.89,1250.05 v1(3230.89,1105.05)
  Bottom Layer w20: v2(3124.06,1592.23) 3221.24,1592.23 3335.89,1477.58 v2(3335.89,1400.05)
VCC_12V: C2.2 C3.2 C10.1 C11.1 C12.1 C13.2 C17.1 J1.3 J1.4 J2.1 Q1.2 R1.2 R11.2 R12.2 U1.3 U3.12 U3.24 | length 4911.9
  Top Layer w10: C17.1 929.2,124.57 1090.74,286.11 R12.2 1090.74,293.99 1101.48,304.73 1155.58,304.73 v2(1245.89,395.05) 1306.92,456.07 U3.12 ; U3.24 1656.84,635.21 1660.53,631.53 1824.42,631.53 1825.89,630.05 v2(2020.89,630.05) ; C10.1@2206.45,1056.07 C10.1 ; R11.2 2487.39,205.05 2499.89,217.55 2499.89,241.29 2528.65,270.05 J2.1
  POWER w10: v2(1245.89,395.05) 1335.89,305.05 1570.89,305.05 1624.4,251.55 1982.39,251.55 2020.89,290.05 v2(2020.89,630.05) 2020.89,825.05 2070.89,875.05 2070.89,1005.05 2094.57,1028.72 2109.57,1028.72 v1(2140.89,1060.05)
  POWER w20: v1(2440.89,1700.05) 2370.89,1630.05 2370.89,1570.05 2445.89,1495.05 2445.89,1332.55 2471.24,1307.2 v1(2471.24,1274.04) ; v1(2450.89,1620.05) 2450.89,1559.52 2476.24,1534.17 2476.24,1511.16 2567.89,1419.51 v1(2567.89,1280.4) ; v1(2554.89,1615.05) 2625.89,1544.05 2625.89,1230.3 2681.55,1174.64 v1(2681.24,1174.64) ; v1(2554.89,1695.05) 2675.89,1574.05 v1(2675.89,1280.4)
  other v1: 2680.89,500.05 2763.39,500.05 2682.2,573.3 2760.39,580.05 2585.89,1174.64 2499.19,1177.23
pads on no net: S1.1 U3.V

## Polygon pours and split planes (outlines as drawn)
AGND on Top Layer "Top Layer-AGND 8" (solid, remove dead copper, pour order 144): -5,2050 2250,2050 2285,2015 2285,1683.74 2583.74,1385 2608.14,1385 2608.14,945.14 2821.21,732.07 2821.21,257.23 2878.66,257.23 2891.24,244.65 2891.24,4.26 0.74,4.26 0,5
AGND on Top Layer "Top Layer-AGND 9" (solid, pour order 138): 1641.24,361.11 1642.36,362.23 1734.87,362.23 1734.87,253.68 1725.74,244.55 1671.24,244.55 1671.24,264.01 1641.27,293.99
AGND on Top Layer "Top Layer-AGND 4" (solid, remove dead copper, pour order 26): 732.82,456.07 732.82,298.12 755.89,275.05 815.89,275.05 825.89,285.05 825.89,340.05 826.72,340.05 835.89,349.22 835.89,400.05 845.89,410.05 875.89,410.05 885.89,420.05 885.89,456.07
SGND on Top Layer "Top Layer-SGND 1" (solid, pour order 132): 3038.71,670.05 3019.51,650.85 3019.51,621.92 3011.46,613.87 2992.7,613.87 2992.7,578.7 3007.77,563.64 3065.01,563.64 3151.24,649.87 3151.24,701.63 3140.89,711.98 3138.96,710.05 3048.81,710.05 3038.71,699.95
SGND on Top Layer "Top Layer-SGND 2" (solid, remove dead copper, pour order 58): 2974.32,712.36 2974.32,848.47 3005.89,880.05 3073.89,880.05 3105.89,848.05 3105.89,800.05 3106.65,800.05 3121.49,785.21 3290.73,785.21 3305.89,770.05 3305.89,742.81 3233.14,670.05 3019.78,670.05 3002.28,687.55 2985.89,687.55 2985.89,700.78
SGND on Top Layer "Top Layer-SGND 3" (solid, remove dead copper, pour order 120): 2306.24,2052.23 3383.56,2052.23 3390.83,2044.97 3390.83,2.71 2892.79,2.71 2891.24,4.26 2894.26,7.28 2894.26,257.23 2821.21,257.23 2785.95,292.49 2785.95,985.05 2773.42,985.05 2616.24,1142.23 2616.24,1431.88 2296.24,1751.88 2296.24,2042.23
Power-DRV on Top Layer "Top Layer-Power-DRV 2" (solid, pour order 136): 195.89,1135.05 300.89,1240.05 300.89,1135.05
VCC_12V on Top Layer "Top Layer-VCC_12V 2" (solid, pour order 122): 2897.63,664.27 2898.41,665.05 2923.52,665.05 2923.52,618.44 2934.73,607.23 2950.89,607.23 2950.89,568.8 2944.32,562.23 2890.58,562.23 2890.58,565.05 2875.27,580.36 2875.27,626.24 2885.58,636.55
AGND on Top Layer "Top Layer-AGND 6" (solid, remove dead copper, pour order 22): 1309.2,425.05 1324.2,440.05 1366.52,440.05 1375.89,430.68 1375.89,347.55 1368.39,340.05 1319.2,340.05 1309.2,350.05
VCC_3.3V on Top Layer "Top Layer-VCC_3.3V" (solid, remove dead copper, pour order 86): 2730.89,1492.69 2793.26,1555.05 2902.64,1555.05 2944.4,1513.3 2944.4,1333.56 2910.89,1300.05 2845.89,1300.05 2795.89,1350.05 2747.33,1350.05 2730.89,1366.49
VCC_3.3V on Top Layer "Top Layer-VCC_3.3V 1" (solid, pour order 100): 2944.4,1513.3 2990.46,1467.23 3113.39,1467.23 3151.24,1429.38 3151.24,1385.8 3127.67,1362.23 2973.07,1362.23 2944.4,1333.56 2942.74,1335.21 2942.74,1370.8
SGND on Top Layer "Top Layer-SGND" (solid, pour order 98): 1475.89,180.55 1500.89,205.55 1500.89,220.05 1619.4,220.05 1650.89,188.55 1650.89,175.05 1704.29,175.05 1791.64,87.7 1791.64,20.05 1490.89,20.05 1490.89,40.05 1475.89,55.05
AGND on Top Layer "Top Layer-AGND" (solid, pour order 96): 1115.89,195.05 1115.89,200.05 1170.89,255.05 1450.89,255.05 1450.89,50.05 1440.89,40.05 1120.89,40.05 1110.89,50.05
VCC_5V on Top Layer "Top Layer-VCC_5V" (solid, remove dead copper, pour order 92): 2690.89,2005.05 2710.89,2025.05 2850.89,2025.05 2865.89,2010.05 2865.89,1780.05 2830.89,1745.05 2725.89,1745.05 2725.89,1752.55 2690.89,1787.55
VCC_12V on Top Layer "Top Layer-VCC_12V" (solid, remove dead copper, pour order 80): 2390.89,1895.05 2390.89,1947.55 2438.39,1995.05 2570.89,1995.05 2595.89,1970.05 2595.89,1605.05 2550.89,1560.05 2430.89,1560.05 2385.89,1605.05 2385.89,1670.05
NetC22_1 on Top Layer "Top Layer-NetC22_1" (solid, remove dead copper, pour order 14): 1545.89,1525.05 1610.74,1460.21 1610.74,1460.05 1775.89,1460.05 1820.2,1415.74 1820.2,1366.49 1871.64,1315.05 1873.06,1316.47 2102.31,1316.47 2135.89,1350.05 2135.89,1452.12 2140.46,1452.12 2173.04,1484.7 2200.54,1484.7 2219.24,1503.4 2219.24,1676.7 2110.89,1785.05 1600.89,1785.05 1550.89,1735.05
NetC19_1 on Top Layer "Top Layer-NetC19_1" (solid, remove dead copper, pour order 10): 832.39,1520.05 845.81,1506.62 989.32,1506.62 1010.89,1485.05 1010.89,1421.7 1027.55,1405.05 1230.89,1405.05 1250.89,1425.05 1410.89,1425.05 1495.89,1510.05 1495.89,1740.05 1410.89,1825.05 1160.89,1825.05 1000.89,1665.05 862.39,1665.05 832.39,1635.05
VCC_12V on Top Layer "Top Layer-VCC_12V 1" (solid, remove dead copper, pour order 16): 2120.89,1305.05 2156.75,1340.91 2156.75,1430.05 2390.89,1430.05 2415.89,1405.05 2415.89,1160.05 2450.89,1125.05 2725.89,1125.05 2775.89,1075.05 2775.89,920.05 2755.89,900.05 2575.89,900.05 2480.89,995.05 2165.14,995.05 2110.89,1049.3 2110.89,1290.05
NetQ3_3 on Top Layer "Top Layer-NetQ3_3" (solid, remove dead copper, pour order 12): 1000.89,1390.05 1010.89,1400.05 1146.64,1400.05 1160.89,1385.8 1160.89,1279.05 1204.89,1235.05 1755.89,1235.05 1848.23,1142.72 1848.23,1098.78 1866.96,1080.05 1930.89,1080.05 1980.89,1130.05 1980.89,1235.05 2035.89,1290.05 2091.25,1290.05 2100.89,1280.4 2095.89,1275.4 2095.89,1170.05 1934.4,1008.55 1706,1008.55 1624.51,1090.05 1068.39,1090.05 1000.89,1157.55
PIN on Top Layer "Top Layer-PIN" (solid, remove dead copper, pour order 76): 570.89,1955.05 338.39,1722.55 338.39,1376.05 379.4,1335.05 478,1335.05 515.89,1372.94 515.89,1540.05 655.89,1680.05 790.89,1680.05 835.89,1725.05 812.19,1748.75 812.19,1931.25 788.39,1955.05
no net on Top Layer "Top Layer-No Net" (solid, pour order 70): 3055.89,667.55
VCC_12V on Top Layer "Top Layer-VCC_12V 3" (solid, remove dead copper, pour order 62): 2415.89,1315.05 2675.89,1315.05 2775.89,1215.05 2775.89,1075.05 2530.89,1075.05 2485.89,1120.05 2415.89,1120.05
VCC_5V on Top Layer "Top Layer-VCC_5V 1" (solid, remove dead copper, pour order 60): 3070.89,1095.05 3115.89,1140.05 3115.89,1175.05 3285.89,1175.05 3335.89,1125.05 3335.89,832.55 3333.57,832.55 3299.82,798.8 3130.89,798.8 3130.89,825.05 3120.89,835.05 3121.49,835.65 3121.49,892.55 3118.39,892.55 3075.89,935.05
VCC_12V on Top Layer "Top Layer-VCC_12V 4" (solid, remove dead copper, pour order 56): 2718.5,683.94 2645.89,611.33 2645.89,331.55 2734.83,242.61 2785.95,242.61 2810.89,267.55 2810.89,659.05 2808.39,661.55
VCC_12V on Top Layer "Top Layer-VCC_12V 5" (solid, remove dead copper, pour order 54): 2635.89,903.05 2677.89,945.05 2735.89,945.05 2735.89,851.54 2680.89,851.54 2680.89,852.55 2635.89,897.55
VCC_12V on Top Layer "Top Layer-VCC_12V 6" (solid, remove dead copper, pour order 52): 2680.89,880.05 2700.89,900.05 2750.89,900.05 2775.89,925.05 2840.89,860.05 2943.39,860.05 2950.89,852.55 2950.89,745.05 2965.89,730.05 2968.02,730.05 2968.02,690.05 2963.02,685.05 2918.41,685.05 2897.63,664.27 2897.63,625.05 2896.33,625.05 2880.89,609.62 2792.82,609.62 2682.39,720.05 2680.89,720.05
no net on Top Layer "Top Layer-No Net 1" (solid, pour order 50): 2695.89,835.05
NetC1_1 on Top Layer "Top Layer-NetC1_1" (solid, remove dead copper, pour order 46): 2799.71,1171.37 2834.71,1206.37 2958.18,1206.37 2992.7,1171.85 2992.7,952.61 2936.46,896.37 2824.71,896.37 2799.71,921.37
NetC1_1 on Top Layer "Top Layer-NetC1_1 1" (solid, remove dead copper, pour order 42): 2950.89,575.36 2956.21,570.05 2987.39,570.05 2993.89,576.55 2993.89,628.04 3010.89,645.05 3010.89,665.05 3005.89,670.05 2942.74,670.05 2932,659.3 2932,640.05 2935.89,640.05 2950.89,625.05
NetC1_1 on Top Layer "Top Layer-NetC1_1 2" (solid, remove dead copper, pour order 40): 3055.89,464.93 3069.27,451.55 3109.39,451.55 3110.89,450.05 3120.89,460.05 3120.89,520.05 3105.89,535.05 3070.89,535.05 3055.89,520.05
AGND on Top Layer "Top Layer-AGND 1" (solid, remove dead copper, pour order 36): 2554.89,150.05 2584.89,180.05 2658.39,180.05 2698.39,220.05 2816.54,220.05 2835.89,200.69 2835.89,85.05 2775.89,25.05 2578.39,25.05 2553.39,50.05
AGND on Top Layer "Top Layer-AGND 2" (solid, remove dead copper, pour order 34): 2147.36,950.05 2150.89,950.05 2180.89,980.05 2480.89,980.05 2554.89,906.05 2554.89,871.05 2580.89,845.05 2735.89,845.05 2760.89,820.05 2760.89,720.05 2735.89,695.05 2490.89,695.05 2375.89,810.05 2175.89,810.05 2175.89,816.51 2147.36,845.05
AGND on Top Layer "Top Layer-AGND 3" (solid, remove dead copper, pour order 32): 348.39,981.05 386.09,1018.75 812.19,1018.75 885.89,945.05 975.89,945.05 990.89,930.05 989.32,928.47 989.32,898.47 972.84,881.99 905.89,881.99 905.89,880.05 780.46,754.61 700.46,754.61 695.89,750.05 680.89,765.05 680.89,817.55 685.89,822.55 668.39,840.05 370.89,840.05 345.89,865.05 348.39,867.55
Power-DRV on Top Layer "Top Layer-Power-DRV 1" (solid, remove dead copper, pour order 30): 300.89,1135.05 195.89,1135.05 120.89,1060.05 120.89,600.05 180.89,540.05 317.51,540.05 365.89,588.44 365.89,805.05 330.89,840.05 330.89,1070.05 345.89,1085.05 345.89,1090.05
AGND on Top Layer "Top Layer-AGND 5" (solid, remove dead copper, pour order 24): 732.82,507.25 745.62,520.05 920.89,520.05 930.89,510.05 930.89,465.05 910.89,445.05 743.85,445.05 732.82,456.07
AGND on Top Layer "Top Layer-AGND 7" (solid, remove dead copper, pour order 20): 1365.89,955.05 1410.89,1000.05 1575.89,1000.05 1592.41,983.53 1592.41,881.99 1535.89,825.48 1531.32,830.05 1394.4,830.05 1370.89,853.55
Power-DRV on Top Layer "Top Layer-Power-DRV" (solid, remove dead copper, pour order 8): 530.89,1470.05 580.89,1520.05 775.89,1520.05 800.89,1495.05 975.89,1495.05 990.89,1480.05 990.89,1225.05 855.89,1090.05 345.89,1090.05 300.89,1135.05 300.89,1265.05 352.31,1316.47 515.89,1316.47 515.89,1318.55 535.89,1338.55
no net on Mechanical 1 (solid): 315.89,300.05
AGND on Bottom Layer "Bottom Layer-AGND" (solid, pour order 146): -5,2050 2250,2050 2285,2015 2285,1683.74 2583.74,1385 2608.14,1385 2608.14,880.05 2821.21,666.98 2821.21,257.23 2878.66,257.23 2891.24,244.65 2891.24,4.26 0.74,4.26 0,5
SGND on Bottom Layer "Bottom Layer-SGND" (solid, remove dead copper, pour order 116): 2306.24,2052.23 3383.56,2052.23 3390.83,2044.97 3390.83,2.71 2892.79,2.71 2891.24,4.26 2894.26,7.28 2894.26,257.23 2821.21,257.23 2785.95,292.49 2785.95,985.05 2773.42,985.05 2616.24,1142.23 2616.24,1431.88 2296.24,1751.88 2296.24,2042.23
SGND on GND (split plane): 3365.64,22.79 2891.51,22.41 2895.98,255.66 2895.95,255.89 2895.98,256.12 2895.8,257.19 2895.68,258.27 2895.6,258.49 2895.56,258.72 2895.12,259.71 2894.72,260.72 2894.59,260.91 2894.49,261.12 2893.81,261.97 2893.16,262.84 2892.98,262.99 2892.83,263.17 2891.95,263.81 2891.1,264.49 2890.89,264.58 2890.7,264.72 2889.68,265.11 2888.69,265.54 2888.46,265.57 2888.24,265.66 2887.16,265.77 2886.09,265.93 2885.86,265.91 2885.62,265.93 2816.9,264.1 2797.17,984.24 2797.15,984.35 2797.16,984.46 2796.94,985.65 2796.75,986.84 2796.71,986.94 2796.69,987.05 2796.17,988.15 2795.68,989.25 2795.61,989.33 2795.56,989.43 2794.78,990.35 2794.02,991.29 2793.93,991.36 2793.86,991.44 2635.9,1134.59 2630.98,1420.22 2630.83,1421.19 2630.76,1422.16 2630.64,1422.49 2630.59,1422.83 2630.2,1423.72 2629.87,1424.64 2629.68,1424.92 2629.54,1425.24 2628.93,1426.01 2628.38,1426.81 2305.98,1783.93 2305.98,2036.28 3356.24,2037.12
AGND on GND (split plane): 2285.81,1780.05 2285.94,1779 2286.03,1777.94 2286.12,1777.7 2286.15,1777.44 2286.56,1776.46 2286.91,1775.46 2287.06,1775.25 2287.16,1775.01 2287.8,1774.16 2288.41,1773.29 2610.87,1416.1 2615.81,1129.88 2615.83,1129.72 2615.82,1129.55 2616.03,1128.42 2616.2,1127.27 2616.26,1127.12 2616.29,1126.96 2616.78,1125.92 2617.25,1124.86 2617.35,1124.73 2617.42,1124.58 2618.16,1123.7 2618.88,1122.8 2619.02,1122.7 2619.12,1122.58 2777.12,979.39 2797.01,253.47 2797.22,252.15 2797.42,250.88 2797.43,250.87 2797.97,249.66 2798.5,248.48 2798.5,248.47 2799.28,247.51 2800.15,246.43 2800.16,246.43 2800.16,246.42 2801.11,245.73 2802.28,244.88 2802.29,244.88 2803.42,244.45 2804.74,243.94 2804.75,243.94 2806.03,243.81 2807.36,243.67 2875.61,245.49 2871.33,22.4 20,20.11 10.6,2034.44 2285.81,2036.26

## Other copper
Top Layer:
  pour cut-out: 927.7,1147.23 989.78,1209.31 989.78,1214.75 992.49,1214.75 996.3,1210.94 996.3,1149.99 1021.24,1125.05 1019.99,1123.8 901.23,1123.8 990.27,1212.84 994.4,1212.84 994.4,1154.86 993.72,1155.54 930.89,1155.54
  pour cut-out: 3051.93,1467.23 3113.39,1467.23 3118.9,1461.72 3116.99,1459.81 3116.99,1457.1 3061.02,1457.1 3051.93,1466.2
  text "北京理工大学-牛牛队-2021-主控板-Ver1" at 1330,1943.15 h30
GND (plane layer: these items are gaps in the copper):
  lines w10: 3175.89,-4.95 3175.89,15.15
  lines w20: 2295.89,2045.05 2295.89,1780.05 2620.89,1420.05 2625.89,1130.05 2787.09,983.97 2807.09,253.75 2885.89,255.85 2880.89,-4.95

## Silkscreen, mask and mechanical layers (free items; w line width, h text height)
Bottom Overlay:
  text "第十六届智能车竞赛-HZG队" at 30,435 h60
Mechanical 1:
  the board outline again, w10

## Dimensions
3376.24,2057.23 to 3385.83,2.71 on Mechanical 1
0,0 to 3385.83,2.71 on Mechanical 1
